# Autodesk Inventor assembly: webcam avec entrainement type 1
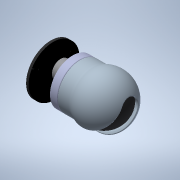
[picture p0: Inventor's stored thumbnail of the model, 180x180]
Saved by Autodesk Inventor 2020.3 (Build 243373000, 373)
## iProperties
Created: 2013-08
Part Number: webcam avec entrainement type 1
Document SubType Name: Assembly
Designer: hilarion
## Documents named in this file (9)
- G:\travail\année 2020-2021\2I2D\Webcam motorisee\webcam avec entrainement type 1.iam
- G:\travail\année 2020-2021\2I2D\Webcam motorisee\Base.ipt
- G:\travail\année 2020-2021\2I2D\Webcam motorisee\Moto-reducteur vertical.ipt
- G:\travail\année 2020-2021\2I2D\Webcam motorisee\Socle.ipt
- G:\travail\année 2020-2021\2I2D\Webcam motorisee\Semelle.ipt
- G:\travail\année 2020-2021\2I2D\Webcam motorisee\cache_réducteur.ipt
- G:\travail\année 2020-2021\2I2D\Webcam motorisee\sortie_moteur.iam
- G:\travail\année 2020-2021\2I2D\Webcam motorisee\Pignon_étagé.iam
- G:\travail\année 2020-2021\2I2D\Webcam motorisee\tête Webcam motorisee.iam
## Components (8 placed, 8 different names)
1. Base:1 — Logement:4, Logement:5, Logement:6
2. Moto-reducteur vertical:1 — Logement:2
3. Socle:1 — Logement:5
4. Semelle:1 — Logement:6
5. cache_réducteur:1 — Logement:1, Logement:3, Logement:4
6. sortie_moteur:1 [sub-assembly] — Logement:2, Rotation:1
7. Pignon_étagé:1 [sub-assembly] — Logement:3, Rotation:1, Rotation:2
8. tête Webcam motorisee:1 [sub-assembly] — Logement:1, Rotation:2
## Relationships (8: Insert 6, RelateRotation 2)
- Logement:1 [Insert]: cache_réducteur:1 ↔ tête Webcam motorisee:1
- Logement:2 [Insert]: Moto-reducteur vertical:1 ↔ sortie_moteur:1
- Logement:3 [Insert]: cache_réducteur:1 ↔ Pignon_étagé:1
- Rotation:1 [RelateRotation]: sortie_moteur:1 ↔ Pignon_étagé:1
- Rotation:2 [RelateRotation]: Pignon_étagé:1 ↔ tête Webcam motorisee:1
- Logement:4 [Insert]: Base:1 ↔ cache_réducteur:1
- Logement:5 [Insert]: Base:1 ↔ Socle:1
- Logement:6 [Insert]: Base:1 ↔ Semelle:1
